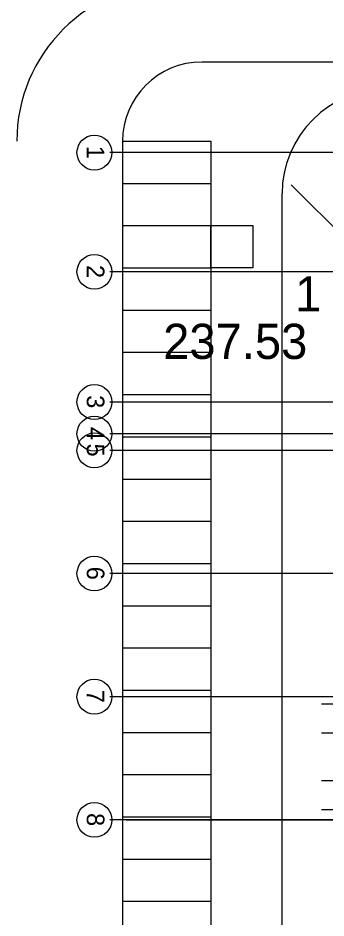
# Model space of a CAD drawing. Extents: x -264165 to -263575, y -1242333 to -1242036.
# Drawn here: x -263927 to -263909.6, y -1242131.5 to -1242080.3 of the extents above; entities that cross this region are included whole.
import ezdxf

# ---------------------------------------------------------------- set-up
doc = ezdxf.new("R2010")
doc.units = 0
for name, color, linetype in [('KFA_BODY_VYTYCOVAK', 7, 'Continuous'), ('KFA_HESCON_OSI_STAVBY', 7, 'Continuous'), ('KFA_SITUACIA_DRS_VYTYCOVAK_SEDA', 7, 'Continuous')]:
    doc.layers.add(name, color=color, linetype=linetype)

msp = doc.modelspace()

# ---------------------------------------------------------------- linework, layer by layer
at = {"layer": 'KFA_HESCON_OSI_STAVBY'}
for p, q in [((-263787.486, -1242087.957), (-263921.823, -1242087.957)), ((-263911.518, -1242089.782), (-263911.518, -1242089.782)), ((-263911.518, -1242089.782), (-263893.465, -1242107.835)), ((-263787.486, -1242094.732), (-263921.823, -1242094.732)), ((-263787.486, -1242102.132), (-263921.823, -1242102.132)), ((-263787.486, -1242103.932), (-263921.823, -1242103.932)), ((-263787.486, -1242104.882), (-263921.823, -1242104.882)), ((-263787.486, -1242111.882), (-263921.823, -1242111.882)), ((-263787.486, -1242118.882), (-263921.823, -1242118.882)), ((-263787.486, -1242125.882), (-263921.823, -1242125.882)), ((-263920.885, -1242125.882), (-263905.505, -1242125.882))]:
    msp.add_line(p, q, dxfattribs=at)
for centre in [(-263922.688, -1242087.956), (-263922.688, -1242094.731), (-263922.688, -1242102.131), (-263922.688, -1242103.931), (-263922.688, -1242104.881), (-263922.688, -1242111.881), (-263922.688, -1242118.881), (-263922.688, -1242125.881)]:
    msp.add_circle(centre, 0.991, dxfattribs=at)
at = {"layer": 'KFA_SITUACIA_DRS_VYTYCOVAK_SEDA'}
for p, q in [((-263808.225, -1242082.808), (-263916.593, -1242082.808)), ((-263921.093, -1242087.308), (-263916.093, -1242087.308)), ((-263921.093, -1242087.308), (-263921.093, -1242241.458)), ((-263916.093, -1242087.308), (-263916.093, -1242141.207)), ((-263921.093, -1242089.707), (-263916.093, -1242089.707)), ((-263912.043, -1242100.14), (-263912.043, -1242090.308)), ((-263921.093, -1242092.107), (-263916.093, -1242092.107)), ((-263916.093, -1242092.107), (-263913.693, -1242092.107)), ((-263916.093, -1242094.507), (-263916.093, -1242092.107)), ((-263916.093, -1242092.107), (-263913.693, -1242092.107)), ((-263916.093, -1242094.507), (-263916.093, -1242092.107)), ((-263913.693, -1242092.107), (-263913.693, -1242094.507)), ((-263913.693, -1242092.107), (-263913.693, -1242094.507)), ((-263921.093, -1242094.507), (-263916.093, -1242094.507)), ((-263913.693, -1242094.507), (-263916.093, -1242094.507)), ((-263913.693, -1242094.507), (-263916.093, -1242094.507)), ((-263921.093, -1242096.907), (-263916.093, -1242096.907)), ((-263921.093, -1242099.307), (-263916.093, -1242099.307)), ((-263912.043, -1242228.625), (-263912.043, -1242100.14)), ((-263921.093, -1242101.707), (-263916.093, -1242101.707)), ((-263921.093, -1242104.107), (-263916.093, -1242104.107)), ((-263921.093, -1242106.507), (-263916.093, -1242106.507)), ((-263921.093, -1242108.907), (-263916.093, -1242108.907)), ((-263921.093, -1242111.307), (-263916.093, -1242111.307)), ((-263921.093, -1242113.707), (-263916.093, -1242113.707)), ((-263921.093, -1242116.107), (-263916.093, -1242116.107)), ((-263921.093, -1242118.507), (-263916.093, -1242118.507)), ((-263908.993, -1242119.307), (-263909.808, -1242119.307)), ((-263908.993, -1242119.307), (-263909.808, -1242119.307)), ((-263921.093, -1242120.907), (-263916.093, -1242120.907)), ((-263908.993, -1242120.957), (-263909.808, -1242120.957)), ((-263908.993, -1242120.957), (-263909.808, -1242120.957)), ((-263921.093, -1242123.307), (-263916.093, -1242123.307)), ((-263908.993, -1242123.657), (-263909.808, -1242123.657)), ((-263908.993, -1242123.657), (-263909.808, -1242123.657)), ((-263921.093, -1242125.707), (-263916.093, -1242125.707)), ((-263908.993, -1242125.307), (-263909.808, -1242125.307)), ((-263908.993, -1242125.307), (-263909.808, -1242125.307)), ((-263921.093, -1242128.107), (-263916.093, -1242128.107)), ((-263921.093, -1242130.507), (-263916.093, -1242130.507))]:
    msp.add_line(p, q, dxfattribs=at)
for centre, radius in [((-263918.093, -1242087.308), 9), ((-263916.593, -1242087.308), 4.5), ((-263906.043, -1242090.308), 6)]:
    msp.add_arc(centre, radius, 90, 180, dxfattribs=at)

# ---------------------------------------------------------------- texts
at = {"layer": 'KFA_BODY_VYTYCOVAK'}
for s, p in [('1', (-263911.3, -1242096.98)), ('237.53', (-263918.79, -1242099.683))]:
    msp.add_text(s, height=2, dxfattribs=at).set_placement(p)
at = {"layer": 'KFA_HESCON_OSI_STAVBY'}
for s, p in [('1', (-263923.123, -1242087.568)), ('2', (-263923.123, -1242094.343)), ('3', (-263923.123, -1242101.743)), ('4', (-263923.123, -1242103.543)), ('5', (-263923.123, -1242104.493)), ('6', (-263923.123, -1242111.493)), ('7', (-263923.123, -1242118.493)), ('8', (-263923.123, -1242125.493))]:
    msp.add_text(s, height=1, rotation=270, dxfattribs=at).set_placement(p)

doc.saveas('drawing.dxf')
